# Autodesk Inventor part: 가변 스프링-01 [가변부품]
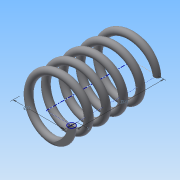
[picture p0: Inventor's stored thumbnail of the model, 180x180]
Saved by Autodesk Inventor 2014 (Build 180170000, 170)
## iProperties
Created: 2015-09
Part Number: 가변 스프링-01 [가변부품]
Material: 강철, 탄소
Document SubType Name: Modeling
Designer: study
Density: 1 g/cm^3
Appearance: 반연마
Author: study
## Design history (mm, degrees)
sketch "스케치1"
  geometry: L1 (0, 0)-(11, 0); L2 (11, 0)-(11, 36.411); L3 (11, 36.411)-(0, 36.411); L4 (0, 36.411)-(0, 0); C1 r 1.5 at (11, 0)
  constraints: 8 end point, 2 parallel, 1 centre point, 1 coincident, 1 horizontal, 1 perpendicular
  dimensions: "d0" = 3 diameter of C1; "d1" = 22 diameter of L2 L4; "d2" = 36.4112 distance of L1.end L2.end (derived)
feature "코일1" sketch "스케치1" pitch "d3" = 10; turns "d5" = 5; dims "d4" = 36.4112 (= d2), "d6" = 0, angle "d7" = 90 deg, angle "d8" = 90 deg, "d9" = 0, "d10" = 0
node "작업 평면1"
sketch "스케치2"
  geometry: L1 (-12.5, 0)-(-9.5, 0) reference; 1 further point
  constraints: 1 horizontal alignment
extrude "돌출1" cut sketch "스케치2" distance "d12" = 10; taper "d13" = 0 deg
node "작업 평면2"
sketch "스케치3"
  geometry: L1 (-9.5, 0)-(-12.5, 0) reference; L2 (-9.5, 0)-(-12.5, 0) reference; 1 further point
  constraints: 2 horizontal alignment
extrude "돌출2" cut sketch "스케치3" distance "d15" = 10; taper "d16" = 0 deg
node "솔리드1"
node "절단 모서리 투영1"
node "절단 모서리 투영2"
node "절단 모서리 투영3"
other parameters: "d11" = 0, "d14" = 36.4112 (= d2)
